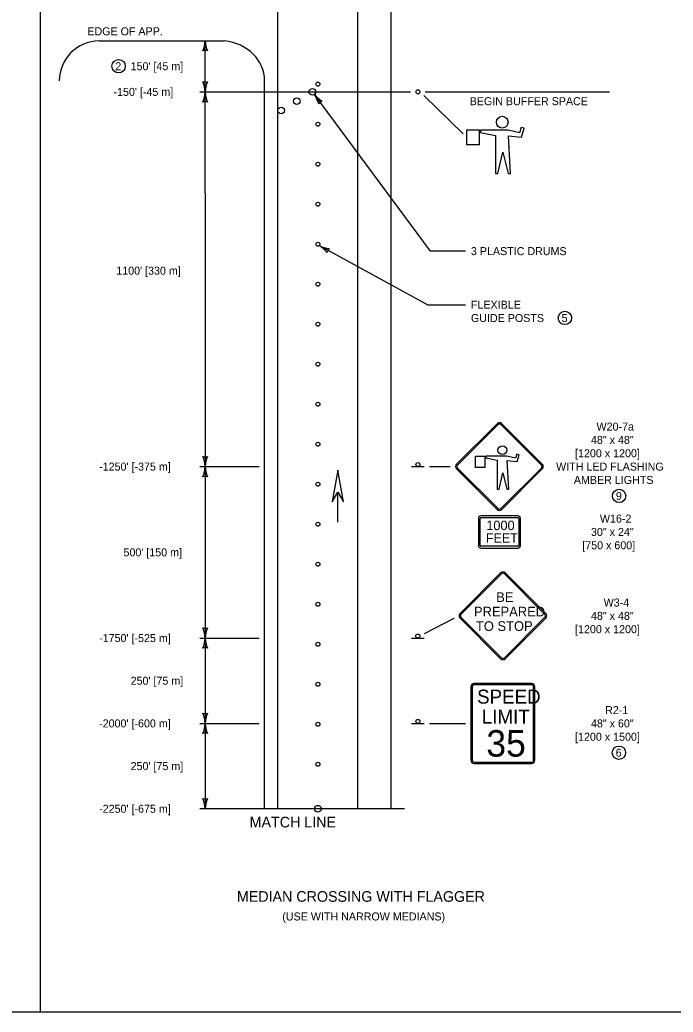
# Model space of a CAD drawing. Extents: x 49991.4 to 50021, y 49987.6 to 50011.4.
# Drawn here: x 50009.03 to 50013.93, y 49987.8 to 49995.24 of the extents above; entities that cross this region are included whole.
import ezdxf

# ---------------------------------------------------------------- set-up
doc = ezdxf.new("R2010")
doc.units = 0
for name, color, linetype in [('Level 1', 7, 'Continuous'), ('Level 10', 7, 'Continuous'), ('Level 2', 7, 'Continuous'), ('Level 3', 7, 'Continuous'), ('Level 6', 7, 'Continuous')]:
    doc.layers.add(name, color=color, linetype=linetype)

msp = doc.modelspace()

# ---------------------------------------------------------------- linework, layer by layer
at = {"layer": 'Level 1'}
for p, q in [((50010.9663, 49989.324), (50010.9663, 49998.3116)), ((50011.5663, 49989.324), (50011.5663, 49998.3116)), ((50011.8163, 49989.324), (50011.8163, 49998.3116)), ((50009.6257, 49995.0822), (50010.5663, 49995.0822)), ((50010.8663, 49989.324), (50010.8663, 49994.7842)), ((50012.3836, 49994.3021), (50012.3836, 49994.4145)), ((50012.3836, 49994.4145), (50012.4755, 49994.4145)), ((50012.4755, 49994.4145), (50012.4755, 49994.3021)), ((50012.6927, 49994.4139), (50012.4858, 49994.4139)), ((50012.4858, 49994.4139), (50012.4858, 49994.3953)), ((50012.7795, 49994.3939), (50012.6927, 49994.4139)), ((50012.7922, 49994.4335), (50012.7795, 49994.3939)), ((50012.8142, 49994.4279), (50012.7922, 49994.4335)), ((50012.7942, 49994.3591), (50012.8142, 49994.4279)), ((50012.4858, 49994.3953), (50012.5983, 49994.3731)), ((50012.5983, 49994.3731), (50012.5983, 49994.0867)), ((50012.7114, 49994.0867), (50012.6966, 49994.3701)), ((50012.6966, 49994.3701), (50012.7942, 49994.3591)), ((50012.4755, 49994.3021), (50012.3836, 49994.3021)), ((50012.6165, 49994.0867), (50012.6548, 49994.2481)), ((50012.6548, 49994.2481), (50012.6931, 49994.0867)), ((50012.5983, 49994.0867), (50012.6165, 49994.0867)), ((50012.6931, 49994.0867), (50012.7114, 49994.0867)), ((50012.6104, 49992.2116), (50012.3063, 49991.9076)), ((50012.6174, 49992.2046), (50012.3134, 49991.9005)), ((50012.9427, 49991.9005), (50012.6387, 49992.2046)), ((50012.9498, 49991.9076), (50012.6457, 49992.2116)), ((50012.4497, 49991.8839), (50012.4497, 49991.9689)), ((50012.4497, 49991.9689), (50012.5192, 49991.9689)), ((50012.5192, 49991.9689), (50012.5192, 49991.8839)), ((50012.6835, 49991.9685), (50012.527, 49991.9685)), ((50012.527, 49991.9685), (50012.527, 49991.9544)), ((50012.527, 49991.9544), (50012.612, 49991.9376)), ((50012.7491, 49991.9533), (50012.6835, 49991.9685)), ((50012.7587, 49991.9833), (50012.7491, 49991.9533)), ((50012.7753, 49991.9791), (50012.7587, 49991.9833)), ((50012.7602, 49991.9271), (50012.7753, 49991.9791)), ((50011.9684, 49991.89), (50012.0644, 49991.89)), ((50012.3134, 49991.8793), (50012.6174, 49991.5752)), ((50012.5192, 49991.8839), (50012.4497, 49991.8839)), ((50012.612, 49991.9376), (50012.612, 49991.7211)), ((50012.6387, 49991.5752), (50012.9427, 49991.8793)), ((50012.6975, 49991.7211), (50012.6863, 49991.9354)), ((50012.6863, 49991.9354), (50012.7602, 49991.9271)), ((50012.3063, 49991.8722), (50012.6104, 49991.5682)), ((50012.6258, 49991.7211), (50012.6547, 49991.8431)), ((50012.6457, 49991.5682), (50012.9498, 49991.8722)), ((50012.6547, 49991.8431), (50012.6837, 49991.7211)), ((50011.416, 49991.4727), (50011.416, 49991.6987)), ((50011.4163, 49991.4727), (50011.4163, 49991.6987)), ((50012.612, 49991.7211), (50012.6258, 49991.7211)), ((50012.6837, 49991.7211), (50012.6975, 49991.7211)), ((50012.7662, 49991.5209), (50012.4896, 49991.5209)), ((50012.4896, 49991.5075), (50012.7662, 49991.5075)), ((50012.4699, 49991.5007), (50012.4699, 49991.2991)), ((50012.483, 49991.2991), (50012.483, 49991.5007)), ((50012.7728, 49991.5007), (50012.7728, 49991.2991)), ((50012.786, 49991.2991), (50012.786, 49991.5007)), ((50012.7662, 49991.2924), (50012.4896, 49991.2924)), ((50012.4896, 49991.279), (50012.7662, 49991.279)), ((50012.6367, 49991.0924), (50012.3326, 49990.7884)), ((50012.6437, 49991.0854), (50012.3397, 49990.7812)), ((50012.969, 49990.7812), (50012.665, 49991.0854)), ((50012.9761, 49990.7884), (50012.672, 49991.0924)), ((50012.3397, 49990.76), (50012.6437, 49990.456)), ((50012.665, 49990.456), (50012.969, 49990.76)), ((50012.3326, 49990.753), (50012.6367, 49990.449)), ((50012.672, 49990.449), (50012.9761, 49990.753)), ((50011.9681, 49990.604), (50012.0641, 49990.604)), ((50012.4143, 49990.239), (50012.4143, 49989.689)), ((50012.4243, 49990.239), (50012.4243, 49989.689)), ((50012.8693, 49990.264), (50012.4393, 49990.264)), ((50012.8693, 49990.254), (50012.4393, 49990.254)), ((50012.8843, 49989.689), (50012.8843, 49990.239)), ((50012.8943, 49989.689), (50012.8943, 49990.239)), ((50011.9683, 49989.964), (50012.0643, 49989.964)), ((50012.4393, 49989.674), (50012.8693, 49989.674)), ((50012.4393, 49989.664), (50012.8693, 49989.664))]:
    msp.add_line(p, q, dxfattribs=at)
for points in [[(49999.3835, 49998.9992), (50016.7501, 49998.9992), (50016.7501, 49987.7988), (49999.3835, 49987.7988)], [(50011.458, 49991.6263), (50011.4163, 49991.8629), (50011.3744, 49991.6263), (50011.4163, 49991.6985)]]:
    msp.add_lwpolyline(points, close=True, dxfattribs=at)
for points in [[(50012.7921, 49994.4333), (50012.7923, 49994.4335)], [(50012.7936, 49994.3593), (50012.7945, 49994.3603)], [(50012.4751, 49994.3021), (50012.4755, 49994.3025)], [(50012.7586, 49991.9831), (50012.7587, 49991.9833)], [(50012.5189, 49991.8839), (50012.5192, 49991.8842)], [(50012.7597, 49991.9272), (50012.7604, 49991.928)]]:
    msp.add_lwpolyline(points, dxfattribs=at)
for centre, radius in [((50011.2248, 49994.7), 0.025), ((50011.2663, 49994.7576), 0.015), ((50012.0163, 49994.7), 0.0152), ((50011.1081, 49994.6301), 0.025), ((50010.9913, 49994.5602), 0.025), ((50012.6491, 49994.4727), 0.0442), ((50011.2663, 49994.4576), 0.015), ((50011.2663, 49994.1576), 0.015), ((50011.2663, 49993.8576), 0.015), ((50011.2663, 49993.5576), 0.015), ((50011.2663, 49993.2576), 0.015), ((50011.2663, 49992.9576), 0.015), ((50011.2663, 49992.6576), 0.015), ((50011.2663, 49992.3576), 0.015), ((50011.2663, 49992.0576), 0.015), ((50012.6504, 49992.013), 0.0334), ((50012.0164, 49991.9052), 0.0152), ((50011.2663, 49991.7576), 0.015), ((50011.2663, 49991.4576), 0.015), ((50011.2663, 49991.1576), 0.015), ((50011.2663, 49990.8576), 0.015), ((50012.0161, 49990.6192), 0.0152), ((50011.2663, 49990.5576), 0.015), ((50011.2663, 49990.2576), 0.015), ((50011.2663, 49989.9576), 0.015), ((50012.0163, 49989.9792), 0.0152), ((50011.2663, 49989.6576), 0.015), ((50011.2667, 49989.3244), 0.025)]:
    msp.add_circle(centre, radius, dxfattribs=at)
for centre, radius, start, end in [((50009.6257, 49994.7821), 0.3, 90, 180), ((50012.6279, 49992.194), 0.025, 45, 135), ((50012.6279, 49992.194), 0.015, 45, 135), ((50012.3239, 49991.89), 0.025, 135, 225), ((50012.3239, 49991.89), 0.015, 135, 225), ((50012.932, 49991.89), 0.015, 315, 45.00024), ((50012.932, 49991.89), 0.025, 315, 45.00024), ((50012.6279, 49991.5859), 0.025, 225, 314.99957), ((50012.6279, 49991.5859), 0.015, 225, 314.99957), ((50012.6543, 49991.0747), 0.025, 45, 135), ((50012.6543, 49991.0747), 0.015, 45, 135), ((50012.3503, 49990.7707), 0.025, 135, 225), ((50012.3503, 49990.7707), 0.015, 135, 225), ((50012.9584, 49990.7707), 0.015, 315, 45.00024), ((50012.9584, 49990.7707), 0.025, 315, 45.00024), ((50012.6543, 49990.4666), 0.025, 225, 314.99957), ((50012.6543, 49990.4666), 0.015, 225, 314.99957), ((50012.4393, 49990.2389), 0.025, 90, 180), ((50012.4393, 49990.2389), 0.015, 90, 180), ((50012.8693, 49990.2389), 0.025, 0, 90), ((50012.8693, 49990.2389), 0.015, 0, 90), ((50012.4393, 49989.6889), 0.025, 180, 270), ((50012.4393, 49989.6889), 0.015, 180, 270), ((50012.8693, 49989.6889), 0.025, 270, 0), ((50012.8693, 49989.6889), 0.015, 270, 0)]:
    msp.add_arc(centre, radius, start, end, dxfattribs=at)
for centre, major_axis, ratio, start_param, end_param in [((50010.5264, 49994.7843), (-0.34, 0), 0.882377, 3.141593, 4.594641), ((50012.4896, 49991.5007), (0, 0.0202), 0.98, 0, 1.570796), ((50012.4896, 49991.5007), (0, 0.00672), 0.98, 0, 1.570796), ((50012.7662, 49991.5007), (0, 0.0202), 0.98, 4.712389, 6.283185), ((50012.7662, 49991.5007), (0, 0.00672), 0.98, 4.712389, 6.283185), ((50012.4896, 49991.2991), (0, -0.0202), 0.98, 4.712389, 6.283185), ((50012.4896, 49991.2991), (0, -0.00672), 0.98, 4.712389, 6.283185), ((50012.7662, 49991.2991), (0, -0.00672), 0.98, 0, 1.570796), ((50012.7662, 49991.2991), (0, -0.0202), 0.98, 0, 1.570796)]:
    msp.add_ellipse(centre, major_axis=major_axis, ratio=ratio, start_param=start_param, end_param=end_param, dxfattribs=at)
at = {"layer": 'Level 10'}
for centre, major_axis, start_param, end_param in [((50010.4175, 49995.0844), (0.00339, 0), 5.889718, 6.241987), ((50010.4209, 49995.0827), (0.000835, 0), 1.25906, 1.882533), ((50010.4244, 49995.0844), (-0.00355, 0), 0.049346, 0.385319)]:
    msp.add_ellipse(centre, major_axis=major_axis, ratio=0.77736, start_param=start_param, end_param=end_param, dxfattribs=at)
at = {"layer": 'Level 2'}
for centre in [(50009.7714, 49994.8921), (50013.1193, 49993.0042), (50013.5261, 49991.6699), (50013.5248, 49989.7444)]:
    msp.add_circle(centre, 0.05, dxfattribs=at)
at = {"layer": 'Level 3'}
for p, q in [((50009.1835, 49998.9992), (50009.1835, 49987.7988)), ((50010.4209, 49994.7), (50010.4209, 49995.0843)), ((50010.4209, 49993.9384), (50010.4209, 49994.7028)), ((50010.3809, 49994.7), (50011.9611, 49994.7)), ((50012.1101, 49993.5057), (50011.2405, 49994.6805)), ((50012.0601, 49994.6719), (50012.3548, 49994.3861)), ((50012.0716, 49994.7), (50013.4543, 49994.7)), ((50010.4209, 49993.9384), (50010.4209, 49991.89)), ((50012.0881, 49993.1039), (50011.2769, 49993.547)), ((50012.3743, 49993.5057), (50012.1101, 49993.5057)), ((50012.0881, 49993.1039), (50012.3743, 49993.1039)), ((50010.3809, 49991.89), (50010.8264, 49991.89)), ((50010.4211, 49991.89), (50010.4211, 49990.604)), ((50012.1044, 49991.89), (50012.2589, 49991.89)), ((50012.0669, 49990.6375), (50012.2897, 49990.7523)), ((50010.3809, 49990.604), (50010.8264, 49990.604)), ((50010.4209, 49990.604), (50010.4209, 49989.964)), ((50010.3809, 49989.964), (50010.8264, 49989.964)), ((50010.4209, 49989.964), (50010.4209, 49989.324)), ((50012.1043, 49989.964), (50012.3743, 49989.964))]:
    msp.add_line(p, q, dxfattribs=at)
for centre, radius, start, end in [((50010.1987, 49995.0931), 0.2223, 337.45601, 357.63952), ((50010.6536, 49995.0954), 0.233, 182.82731, 202.07716), ((50010.4209, 49994.9557), 0.0548, 72.13882, 107.86118), ((50010.4209, 49994.8282), 0.0548, 252.13882, 287.86118), ((50010.1882, 49994.6885), 0.233, 2.82731, 22.07716), ((50010.643, 49994.6908), 0.2223, 157.45601, 177.63952), ((50010.1988, 49994.7091), 0.2223, 337.45601, 357.63952), ((50010.6536, 49994.7114), 0.233, 182.82731, 202.07716), ((50011.0565, 49994.5557), 0.2223, 13.9674, 34.15091), ((50011.4207, 49994.8282), 0.233, 219.3387, 238.58855), ((50011.3168, 49994.5774), 0.0548, 108.65021, 144.37257), ((50010.4209, 49994.5717), 0.0548, 72.13882, 107.86118), ((50011.3738, 49993.7466), 0.2223, 244.09582, 264.27933), ((50011.1564, 49993.3471), 0.233, 39.65818, 58.90803), ((50011.3896, 49993.4859), 0.0548, 133.87416, 169.59652), ((50010.4209, 49992.0182), 0.0548, 252.13882, 287.86118), ((50010.1882, 49991.8785), 0.233, 2.82731, 22.07716), ((50010.643, 49991.8808), 0.2223, 157.45601, 177.63952), ((50010.1882, 49991.9015), 0.233, 337.92284, 357.17269), ((50010.643, 49991.8992), 0.2223, 182.36048, 202.54399), ((50010.4209, 49991.7618), 0.0548, 72.13882, 107.86118), ((50010.4209, 49990.7322), 0.0548, 252.13882, 287.86118), ((50010.1882, 49990.5925), 0.233, 2.82731, 22.07716), ((50010.643, 49990.5948), 0.2223, 157.45601, 177.63952), ((50010.1988, 49990.6132), 0.2223, 337.45601, 357.63952), ((50010.6536, 49990.6155), 0.233, 182.82731, 202.07716), ((50010.4209, 49990.4758), 0.0548, 72.13882, 107.86118), ((50010.4209, 49990.0922), 0.0548, 252.13882, 287.86118), ((50010.1882, 49989.9525), 0.233, 2.82731, 22.07716), ((50010.643, 49989.9548), 0.2223, 157.45601, 177.63952), ((50010.1988, 49989.9731), 0.2223, 337.45601, 357.63952), ((50010.6536, 49989.9754), 0.233, 182.82731, 202.07716), ((50010.4209, 49989.8357), 0.0548, 72.13882, 107.86118), ((50010.4209, 49989.4522), 0.0548, 252.13882, 287.86118), ((50010.1882, 49989.3125), 0.233, 2.82731, 22.07716), ((50010.643, 49989.3148), 0.2223, 157.45601, 177.63952)]:
    msp.add_arc(centre, radius, start, end, dxfattribs=at)
at = {"layer": 'Level 6'}
msp.add_line((50011.9163, 49989.324), (50010.3809, 49989.324), dxfattribs=at)

# ---------------------------------------------------------------- texts
at = {"layer": 'Level 1'}
for s, height, p in [('1000', 0.07124, (50012.5299, 49991.4134)), ('FEET', 0.06989, (50012.5267, 49991.3193)), ('BE', 0.0725, (50012.604, 49990.875)), ('PREPARED', 0.0725, (50012.4371, 49990.7662)), ('TO STOP', 0.0725, (50012.4518, 49990.6576)), ('SPEED', 0.10512, (50012.4604, 49990.1122)), ('LIMIT', 0.10512, (50012.4959, 49989.9622)), ('35', 0.19892, (50012.5299, 49989.7148))]:
    msp.add_text(s, height=height, dxfattribs=at).set_placement(p)
at = {"layer": 'Level 2'}
for s, height, p in [('EDGE OF APP.', 0.06, (50009.5365, 49995.1242)), ("150' [45 m]", 0.06, (50009.8614, 49994.8621)), ('2', 0.06, (50009.7462, 49994.8621)), ("-150' [-45 m]", 0.06, (50009.7328, 49994.67)), ('BEGIN BUFFER SPACE', 0.06, (50012.4048, 49994.6)), ('3 PLASTIC DRUMS', 0.06, (50012.4143, 49993.4757)), ("1100' [330 m]", 0.06, (50009.7536, 49993.329)), ('FLEXIBLE', 0.06, (50012.4143, 49993.0739)), ('GUIDE POSTS', 0.06, (50012.4143, 49992.9739)), ('5', 0.06, (50013.0944, 49992.9742)), ('W20-7a', 0.06, (50013.3564, 49992.1599)), ('48" x 48"', 0.06, (50013.3149, 49992.0599)), ('[1200 x 1200]', 0.06, (50013.1955, 49991.9599)), ("-1250' [-375 m]", 0.06, (50009.6251, 49991.86)), ('WITH LED FLASHING', 0.06, (50013.0533, 49991.8599)), ('AMBER LIGHTS', 0.06, (50013.1864, 49991.7599)), ('9', 0.06, (50013.5015, 49991.6399)), ('W16-2', 0.06, (50013.3818, 49991.4699)), ('30" x 24"', 0.06, (50013.3149, 49991.3699)), ("500' [150 m]", 0.06, (50009.8078, 49991.217)), ('[750 x 600]', 0.06, (50013.2494, 49991.2699)), ('W3-4', 0.06, (50013.4099, 49990.8406)), ('48" x 48"', 0.06, (50013.3149, 49990.7406)), ('[1200 x 1200]', 0.06, (50013.1955, 49990.6406)), ("-1750' [-525 m]", 0.06, (50009.6251, 49990.574)), ("250' [75 m]", 0.06, (50009.8614, 49990.254)), ('R2-1', 0.06, (50013.4205, 49990.034)), ("-2000' [-600 m]", 0.06, (50009.6251, 49989.934)), ('48" x 60"', 0.06, (50013.3149, 49989.934)), ('[1200 x 1500]', 0.06, (50013.1955, 49989.834)), ('6', 0.06, (50013.5003, 49989.7144)), ("250' [75 m]", 0.06, (50009.8614, 49989.614)), ("-2250' [-675 m]", 0.06, (50009.6251, 49989.294)), ('MATCH LINE', 0.08, (50010.7542, 49989.184)), ('MEDIAN CROSSING WITH FLAGGER', 0.08, (50010.6588, 49988.6264)), ('(USE WITH NARROW MEDIANS)', 0.06, (50010.9992, 49988.4864))]:
    msp.add_text(s, height=height, dxfattribs=at).set_placement(p)

doc.saveas('drawing.dxf')
